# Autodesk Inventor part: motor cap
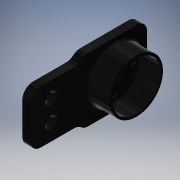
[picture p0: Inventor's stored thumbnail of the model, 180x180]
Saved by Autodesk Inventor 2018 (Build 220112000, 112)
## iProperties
Created: 2023-12
Part Number: motor cap
Material: Generic
Document SubType Name: Modeling
Designer: DDUGKY
Density: 1 g/cm^3
Appearance: Default
Author: DDUGKY
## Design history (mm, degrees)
sketch "Sketch1"
  geometry: C1 r 22.625 at (0, 0); C2 r 25 at (0, 0)
  constraints: 2 centre point, 1 coincident
  dimensions: "d2" = 45.25 diameter of C1; "d3" = 50 diameter of C2
extrude "Extrusion1" new body sketch "Sketch1" distance "d4" = 20; taper "d5" = 0 deg
sketch "Sketch2"
  geometry: L1 (30, 30)-(-30, 30); L2 (-30, -30)-(30, -30); L3 (30, -30)-(30, 30); L4 (30, 30)-(-30, -30); L5 (-30, 30)-(30, -30); L6 (-30, 25)-(-80, 25); L7 (-80, 25)-(-80, -25); L8 (-80, -25)-(-30, -25); L9 (-30, 25)-(-80, -25); L10 (-80, 25)-(-30, -25); L11 (-30, 30)-(-30, 25); L12 (-30, -30)-(-30, -25); 2 further points
  constraints: 24 end point, 4 midpoint, 2 horizontal, 2 parallel, 2 vertical, 1 perpendicular
  dimensions: "d6" = 60 distance of L2.end L2.start; "d7" = 60 distance of L2.start L1.end; "d8" = 50 distance of L8.end L7.end; "d9" = 50 distance of L7.end L6.end
extrude "Extrusion2" join sketch "Sketch2" distance "d10" = 7.5; taper "d11" = 0 deg
sketch "Sketch3"
  geometry: C1 r 6.25 at (0, 0); 1 further point
  constraints: 1 centre point, 1 coincident
  dimensions: "d12" = 12.5 diameter of C1
extrude "Extrusion3" cut sketch "Sketch3" stored distance "d13" = 537.5; taper "d14" = 0 deg
sketch "Sketch4" dims "d15" = 35
  geometry: C1 r 2 at (0, 17.5); 2 further points
  constraints: 1 centre point, 1 coincident, 1 vertical alignment, 2 other
  dimensions: "d16" = 4 diameter of C1
extrude "Extrusion4" cut sketch "Sketch4" stored distance "d17" = 206.25; taper "d18" = 0 deg
pattern_circular "Circular Pattern1" dims angle "d20" = 360 deg
sketch "Sketch5"
  geometry: L1 (0, 0)-(0, -60); L2 (0, -60)-(-10, -60); L3 (0, -60)-(10, -60); C1 r 25 at (0, 0) reference; C2 r 3.75 at (-10, -60); C3 r 3.75 at (10, -60); 1 further point
  constraints: 6 end point, 2 centre point, 2 coincident, 2 symmetric about line, 1 perpendicular, 1 vertical, 1 other
  dimensions: "d22" = 60 distance of L1.start L1.end; "d23" = 10 distance of L1.end L2.end; "d24" = 7.5 diameter of C2
extrude "Extrusion5" cut sketch "Sketch5" stored distance "d25" = 104.5; taper "d26" = 0 deg
chamfer "Chamfer1" distance "d27" = 2; stored, may be unused: second distance "d28" = 2, angle "d29" = 45 deg
chamfer "Chamfer2" distance "d30" = 2; stored, may be unused: second distance "d31" = 2, angle "d32" = 45 deg
chamfer "Chamfer3" distance "d33" = 2; stored, may be unused: second distance "d34" = 2, angle "d35" = 45 deg
fillet "Fillet1" dims "d36" = 2
fillet "Fillet2" dims "d37" = 10
sketch "Sketch6"
  geometry: C1 r 3.75 at (-10, -60) reference; C2 r 3.75 at (-10, -60); C3 r 7.5 at (-10, -60); C4 r 3.75 at (10, -60) reference; C5 r 3.75 at (10, -60); C6 r 7.5 at (10, -60); 1 further point
  constraints: 4 centre point, 4 coincident, 1 equal radius
  dimensions: "d38" = 15 diameter of C3
extrude "Extrusion6" join sketch "Sketch6" distance "d39" = 2.5; taper "d40" = 0 deg
sketch "Sketch7"
  geometry: C1 r 10 at (0, 0); C2 r 6.25 at (0, 0); 1 further point
  constraints: 2 centre point, 2 coincident
  dimensions: "d41" = 20 diameter of C1
extrude "Extrusion7" join sketch "Sketch7" distance "d42" = 10; taper "d43" = 0 deg
body "Solid1"
